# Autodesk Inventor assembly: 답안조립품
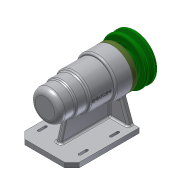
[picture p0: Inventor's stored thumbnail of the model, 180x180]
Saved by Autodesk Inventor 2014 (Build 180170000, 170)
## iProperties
Created: 2017-09
Part Number: 답안조립품
Document SubType Name: Assembly
Designer: user
Author: user
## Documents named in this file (12)
- C:\Users\user\Desktop\470908V1001\답안조립품.iam
- C:\Users\user\Desktop\470908V1001\본체.ipt
- C:\Users\user\Desktop\470908V1001\축.ipt
- C:\Users\user\Desktop\470908V1001\키 5 x 5 x 16.ipt
- C:\Users\user\Desktop\470908V1001\V벨트풀리.ipt
- C:\Users\user\Desktop\470908V1001\멈춤나사 M3x8.ipt
- C:\Users\user\Desktop\470908V1001\베어링 6004.ipt
- C:\Users\user\Desktop\470908V1001\볼트 M4 x 12.ipt
- C:\Users\user\Desktop\470908V1001\베어링 51202.ipt
- C:\Users\user\Desktop\470908V1001\어댑터슬리브.ipt
- C:\Users\user\Desktop\470908V1001\커버.ipt
- C:\Users\user\Desktop\470908V1001\오일 실 20x35x7.ipt
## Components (1 placed, 1 different names)
1. V벨트풀리:1
